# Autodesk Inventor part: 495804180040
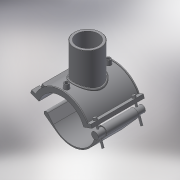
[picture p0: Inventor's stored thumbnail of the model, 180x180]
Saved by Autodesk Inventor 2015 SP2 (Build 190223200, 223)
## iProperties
Created: 2017-07
Part Number: 495804180040
Material: Generic
Description: PLASSON BRANCH SADDLE 180-40
Document SubType Name: Modeling
Designer: KIM
Density: 1 g/cm^3
Appearance: Default
Author: KIM
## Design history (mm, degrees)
derived "495804.ipt"
feature "Solid1::495804.ipt"
feature "Solid2::495804.ipt"
tag "TaggingFeature1"
body "Solid1"
body "Solid2"
other parameters: "d2" = 219, "d3" = 45, "d4" = 118, "d5" = 0, "d6" = 0.1, "d8" = 0, "d19" = 6, "d20" = 6, "d21" = 70.8, "d23" = 0, "d24" = 35.4, "d26" = 0, "d27" = 3, "d28" = 3, "d29" = 3, "d31" = 6, "d32" = 0, "d33" = 0, "d34" = 0.6, "d40" = 104, "d41" = 44, "d43" = 0, "d45" = 0, "d47" = 178, "d50" = 0, "d70" = 15, "d72" = 0, "d73" = 6, "d75" = 5, "d76" = 0, "d77" = 9, "d79" = 15, "d80" = 47.2, "d82" = 5 deg, "d84" = 4, "d85" = 14, "d86" = 0, "d87" = 3, "d88" = 0, "d89" = 1, "d90" = 1, "d91" = 94.4, "d92" = 0, "d93" = 0.5, "d94" = 94.73684, "d96" = 204, "d97" = 2.36, "d98" = 0, "d102" = 1.2, "d103" = 32, "d105" = 0, "d109" = -26, "d117" = 0.4, "d120" = 140 deg, "d121" = 24.228, "d122" = 20 deg, "d126" = 0, "d143" = 189, "d150" = 32.4, "d159" = 4, "d161" = 4.5, "d162" = 70.8, "d163" = 0, "d167" = 36, "d168" = 90.90909, "d173" = 1, "d176" = 20 deg, "d177" = 12.6, "d180" = 0, "d185" = 38.35, "d186" = 38.35, "d188" = 6, "d189" = 12.6, "d190" = 0, "d202" = 0, "d216" = 106.2, "d217" = 0, "d221" = 43.66, "d222" = 12.6, "d223" = 7.56, "d225" = 7.56, "d227" = 25.92, "d230" = 111.6, "d236" = 20 deg, "d237" = 107, "d238" = 20 deg, "d239" = 12.6, "B_" = 219, "H_" = 78, "L_" = 118, "d_t" = 6, "H_1" = 68, "d148" = 4.5, "d160" = 4.5
